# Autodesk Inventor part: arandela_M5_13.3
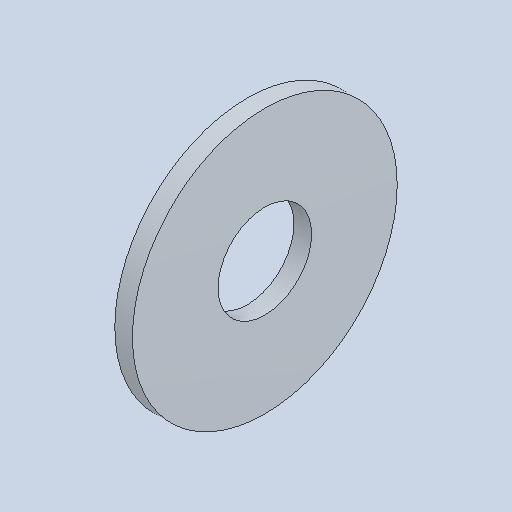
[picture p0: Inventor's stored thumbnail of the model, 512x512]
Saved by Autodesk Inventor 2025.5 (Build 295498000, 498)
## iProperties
Created: 2026-10
Part Number: arandela_M5_13.3
Material: Genérico
Document SubType Name: Modeling
Designer: Luis M
Density: 1 g/cm^3
Appearance: Valor por defecto
Author: Luis M
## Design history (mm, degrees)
feature "Base1"
node "Sólido1"
